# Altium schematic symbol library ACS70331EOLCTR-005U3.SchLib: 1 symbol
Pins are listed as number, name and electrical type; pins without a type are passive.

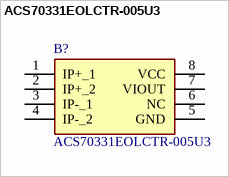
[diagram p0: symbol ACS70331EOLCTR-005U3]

## ACS70331EOLCTR-005U3
designator B?
High Sensitivity, Gmr-Based Current Sensor IC; Manufacturer_Name: Allegro Microsystems; Geometry.Height: 1.75mm
footprint SOIC127P600X175-8N
pins: 1 IP+_1, 2 IP+_2, 3 IP-_1, 4 IP-_2, 5 GND, 6 NC, 7 VIOUT, 8 VCC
